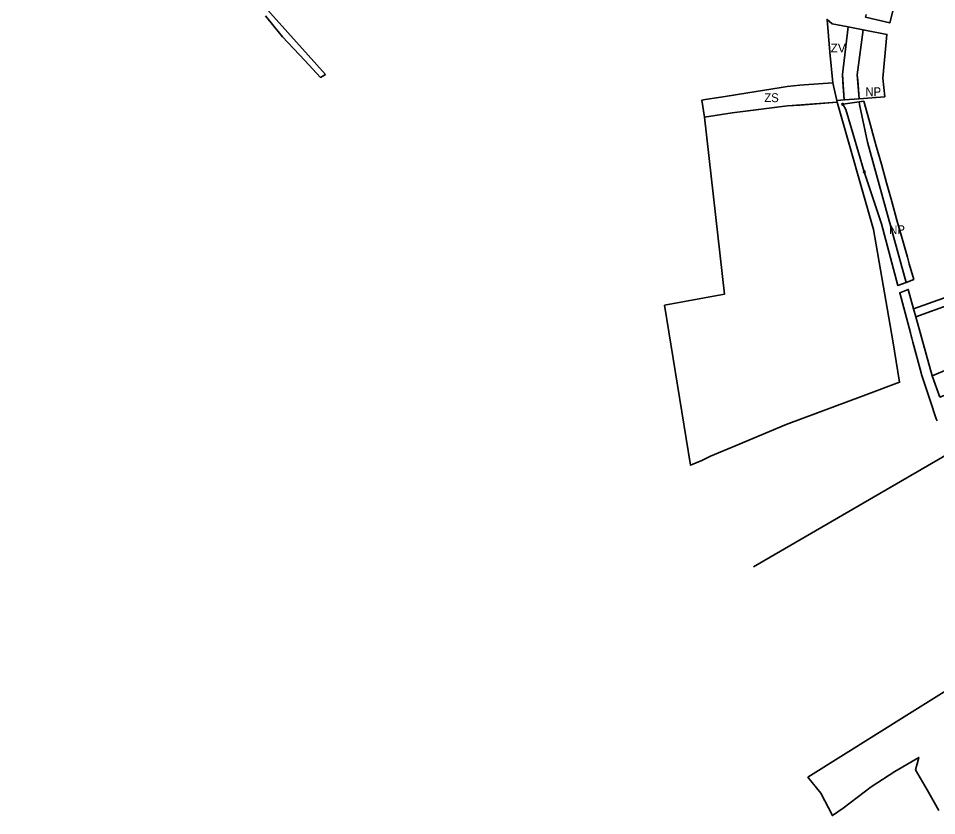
# Model space of a CAD drawing. Extents: x -650276 to -642489, y -1074311 to -1066658.
# Drawn here: x -650258 to -649019, y -1071348 to -1070272 of the extents above; entities that cross this region are included whole.
import ezdxf

# ---------------------------------------------------------------- set-up
doc = ezdxf.new("R2010")
doc.units = 0
doc.header["$LTSCALE"] = 4.8
doc.header["$PDMODE"] = 32
doc.header["$PDSIZE"] = 2.4
for name, color, linetype, lineweight in [('2', 7, 'Continuous', 35), ('24', 7, 'Continuous', 35), ('40', 7, 'Continuous', 35), ('41', 7, 'Continuous', 35), ('48', 7, 'Continuous', 35), ('54', 7, 'Continuous', 35)]:
    doc.layers.add(name, color=color, linetype=linetype, lineweight=lineweight)
doc.layers.add('62', color=7, linetype='Continuous')

msp = doc.modelspace()

# ---------------------------------------------------------------- linework, layer by layer
at = {"layer": '2'}
msp.add_lwpolyline([(-649332.2, -1070405.42), (-649294.79, -1070399.65), (-649220.16, -1070390.26), (-649153.11, -1070385.21), (-649104, -1070557), (-649078, -1070707), (-649069, -1070763), (-649118.07, -1070781.42), (-649221.94, -1070820.12), (-649289.37, -1070848.48), (-649324.21, -1070862.51), (-649335.72, -1070868.73), (-649351, -1070875), (-649386, -1070659), (-649305, -1070644)], close=True, dxfattribs=at)
msp.add_lwpolyline([(-649015.83, -1071340.58), (-649031.91, -1071312.65), (-649047.3, -1071285.92), (-649045.19, -1071277.86), (-649042.927, -1071269.216), (-649075.6, -1071288.29), (-649107.36, -1071308.9), (-649144.99, -1071337.61), (-649159.64, -1071347.68), (-649175.1, -1071317.29), (-649192.568, -1071295.954), (-649055.64, -1071209.682), (-648966.9, -1071154.34)], dxfattribs=at)
at = {"layer": '24'}
msp.add_line((-649146.163, -1070347.543), (-649145.424, -1070357.637), dxfattribs=at)
for points in [[(-649138.43, -1070283.6), (-649146.163, -1070347.543), (-649146.163, -1070347.543), (-649145.424, -1070357.637)], [(-649125.503, -1070355.837), (-649126.069, -1070348.097), (-649118.257, -1070287.455), (-649138.43, -1070283.6), (-649146.163, -1070347.543)], [(-649125.503, -1070355.837), (-649126.069, -1070348.097), (-649118.257, -1070287.455), (-649138.43, -1070283.6)], [(-649145.424, -1070357.637), (-649143.633, -1070382.123), (-649123.693, -1070380.572), (-649125.503, -1070355.837)], [(-649145.424, -1070357.637), (-649143.633, -1070382.123), (-649123.693, -1070380.572), (-649125.503, -1070355.837)], [(-649059.951, -1070628.223), (-649112.14, -1070439.152), (-649123.138, -1070388.16), (-649123.385, -1070384.775), (-649145.73, -1070387.91)], [(-649145.73, -1070387.91), (-649141.48, -1070394.84), (-649132.07, -1070426.81), (-649116.56, -1070479.19)], [(-649116.56, -1070479.19), (-649093.2, -1070549.1), (-649071.33, -1070632.6), (-649059.951, -1070628.223)], [(-649014.888, -1070782.994), (-649025.129, -1070754.377), (-649047.11, -1070674.743), (-649050.081, -1070663.981), (-649057.338, -1070637.689), (-649068.65, -1070642.23), (-649068.65, -1070642.23), (-649054.31, -1070696.44), (-649052.77, -1070702.25), (-649052.44, -1070703.48), (-649051.03, -1070708.74), (-649040.03, -1070750.06), (-649039.38, -1070752.51), (-649039.06, -1070753.72), (-649038.51, -1070755.38), (-649027.74, -1070787.51), (-649027.64, -1070787.8), (-649019.48, -1070812.18), (-649018.48, -1070815.18)]]:
    msp.add_lwpolyline(points, dxfattribs=at)
for p in [(-649145.73, -1070387.91), (-649116.56, -1070479.19)]:
    msp.add_point(p, dxfattribs=at)
at = {"layer": '40'}
msp.add_lwpolyline([(-649138.43, -1070283.6), (-649159.78, -1070279.52), (-649166.86, -1070273.48), (-649162.91, -1070317.47), (-649159.19, -1070358.82), (-649153.64, -1070382.9), (-649148.23, -1070382.48), (-649143.633, -1070382.123), (-649146.163, -1070347.543)], close=True, dxfattribs=at)
at = {"layer": '41'}
msp.add_lwpolyline([(-649159.19, -1070358.82), (-649197.91, -1070361.8), (-649203.4, -1070362.23), (-649220.47, -1070363.94), (-649231.39, -1070365.69), (-649273.57, -1070372.44), (-649304.18, -1070377.35), (-649331.3, -1070381.69), (-649335.79, -1070382.41), (-649332.2, -1070405.42), (-649294.79, -1070399.65), (-649269.769, -1070396.502), (-649220.16, -1070390.26), (-649202.969, -1070388.965), (-649153.11, -1070385.21), (-649153.64, -1070382.9)], close=True, dxfattribs=at)
at = {"layer": '48'}
for points in [[(-649924.15, -1070268.55), (-649913.03, -1070282.44), (-649901.59, -1070296.73), (-649871.28, -1070329.01), (-649850.04, -1070351.64), (-649843.513, -1070347.685), (-650257.713, -1069885.547)], [(-649114.172, -1070266.777), (-649114.931, -1070270.621), (-649082.233, -1070278.265), (-649036.031, -1070097.854), (-649057.722, -1070089.665), (-649067.061, -1070085.844)], [(-649089.07, -1070377.88), (-649091.46, -1070352.73), (-649086.157, -1070293.589), (-649118.257, -1070287.455), (-649126.069, -1070348.097)], [(-649126.069, -1070348.097), (-649123.693, -1070380.572), (-649089.07, -1070377.88)]]:
    msp.add_lwpolyline(points, dxfattribs=at)
for points in [[(-649059.951, -1070628.223), (-649049.96, -1070624.38), (-649055.93, -1070603.08), (-649058.38, -1070594.33), (-649065.42, -1070569.21), (-649072.47, -1070544.09), (-649079.51, -1070518.97), (-649086.55, -1070493.85), (-649093.59, -1070468.73), (-649100.01, -1070445.82), (-649102.31, -1070437.61), (-649109.76, -1070411.05), (-649117.36, -1070383.93), (-649123.385, -1070384.775), (-649123.138, -1070388.16), (-649112.14, -1070439.152)], [(-649014.888, -1070782.994), (-648966.35, -1070764.7), (-648908.94, -1070740.19), (-648892.215, -1070733.293), (-648927.2, -1070637.98), (-648941.064, -1070599.735), (-648965.569, -1070610.382), (-648956.687, -1070630.825), (-649050.081, -1070663.981), (-649047.11, -1070674.743), (-648952.455, -1070640.564), (-648922.196, -1070710.207), (-648924.668, -1070712.022), (-648943.837, -1070720.104), (-649025.129, -1070754.377)]]:
    msp.add_lwpolyline(points, close=True, dxfattribs=at)
at = {"layer": '54'}
msp.add_line((-649003.638, -1070859.543), (-649266.084, -1071012.071), dxfattribs=at)

# ---------------------------------------------------------------- texts
at = {"layer": '62'}
msp.add_text('ZV', height=12, dxfattribs=at).set_placement((-649162.076, -1070318.026))
at = {"layer": '62', "width": 0.95}
for s, p in [('ZS', (-649251.482, -1070385.05)), ('NP', (-649115.076, -1070377.026)), ('NP', (-649082.942, -1070563.157))]:
    msp.add_text(s, height=12, dxfattribs=at).set_placement(p)

doc.saveas('drawing.dxf')
